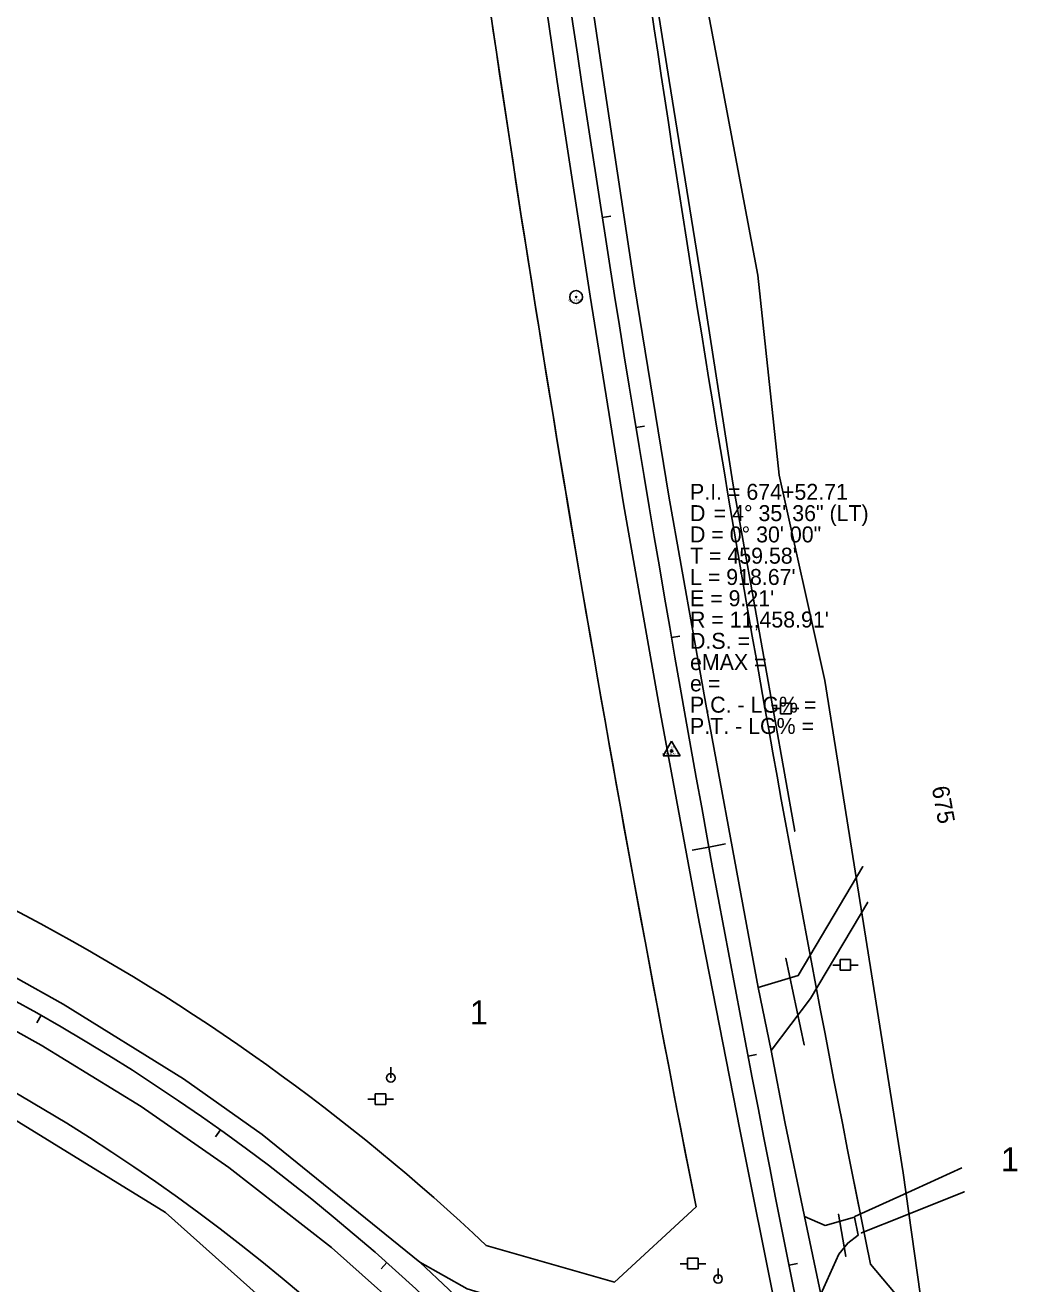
# Model space of a CAD drawing. Extents: x 2519952 to 2531965, y 848341 to 887632.
# Drawn here: x 2523719 to 2524187, y 857916 to 858508 of the extents above; entities that cross this region are included whole.
import ezdxf

# ---------------------------------------------------------------- set-up
doc = ezdxf.new("R2010")
doc.units = 0
for name, color, linetype in [('RD_EX_DR_Pipe', 7, 'Continuous'), ('RD_EX_Driveway', 7, 'Continuous'), ('RD_EX_DV_Prop', 7, 'Continuous'), ('RD_EX_DV_TX_Prop', 7, 'Continuous'), ('RD_EX_Fence_Other', 7, 'Continuous'), ('RD_EX_Road', 7, 'Continuous'), ('RD_EX_RW', 7, 'Continuous'), ('RD_EX_UT', 7, 'Continuous'), ('RD_EX_VEG', 7, 'Continuous'), ('RD_HC_Cl', 7, 'Continuous'), ('RD_HC_Data', 7, 'Continuous'), ('RD_HC_Data_Tic', 7, 'Continuous'), ('RD_HC_Survey_txCode', 7, 'Continuous'), ('RD_HC_TX_Sta50', 7, 'Continuous'), ('RD_HC_txCode', 7, 'Continuous'), ('RD_SMD_Locator', 7, 'Continuous')]:
    doc.layers.add(name, color=color, linetype=linetype)

msp = doc.modelspace()

# ---------------------------------------------------------------- linework, layer by layer
at = {"layer": 'RD_EX_DR_Pipe'}
for p, q in [((2524084.73, 858028.68), (2524076.07, 858069.38)), ((2524104.27, 857929.3), (2524100.83, 857949.12))]:
    msp.add_line(p, q, dxfattribs=at)
at = {"layer": 'RD_EX_Driveway'}
for points in [[(2524063.02, 858055.62), (2524081.9, 858061.29), (2524112.29, 858112.46)], [(2524069.13, 858026.03), (2524087.62, 858050.5), (2524114.54, 858095.72)], [(2524108.43, 857947.98), (2524131.43, 857958.46), (2524158.73, 857970.91)], [(2524111.57, 857940.3), (2524132.07, 857948.51), (2524159.92, 857959.65)], [(2524092.56, 857911.62), (2524100.98, 857930.33), (2524105.25, 857935.59), (2524110.11, 857939.35), (2524108.3, 857947.72), (2524094.5, 857943.84), (2524084.8, 857948.12)]]:
    msp.add_lwpolyline(points, dxfattribs=at)
at = {"layer": 'RD_EX_DV_Prop'}
for p, q in [((2523718.75, 858089.43), (2522948.36, 858496.8)), ((2523995.66, 857917.22), (2524033.94, 857952.52)), ((2523935.39, 857934.44), (2523995.66, 857917.22)), ((2524115.79, 857925.6), (2524172.55, 857858.94))]:
    msp.add_line(p, q, dxfattribs=at)
for centre, radius, start, end in [((2535312.3, 860182.25), 11421.66, 187.82505, 191.395271), ((2535312.3, 860182.25), 11496.66, 187.82505, 191.183137), ((2523254.83, 857212.11), 992.43, 46.70549, 62.13073), ((2523254.83, 857212.11), 917.43, 12.4185, 62.13074)]:
    msp.add_arc(centre, radius, start, end, dxfattribs=at)
at = {"layer": 'RD_EX_Fence_Other'}
msp.add_lwpolyline([(2524080.31, 858129.09), (2524051.13, 858292.53), (2524036.38, 858388.51), (2524021.25, 858481.81), (2524005.1, 858583.36), (2523991.56, 858679.34), (2523981.61, 858745.39), (2523956.83, 858911.5), (2524009.65, 858983.89), (2524009.65, 858983.89), (2524012.84, 858990.17), (2524066.54, 859070.76), (2524113.94, 859137)], dxfattribs=at)
at = {"layer": 'RD_EX_Road'}
for p, q in [((2523990.7, 858479.78), (2523975.78, 858582.23)), ((2523969.29, 858477.11), (2523954.67, 858578.35)), ((2524005.03, 858385.29), (2523990.7, 858479.78)), ((2523984.15, 858380.4), (2523969.29, 858477.11)), ((2524021.05, 858286.44), (2524005.03, 858385.29)), ((2523999.9, 858282.83), (2523984.15, 858380.4)), ((2524038.56, 858188.75), (2524021.05, 858286.44)), ((2524017.21, 858184.41), (2523999.9, 858282.83)), ((2524035.31, 858086.37), (2524017.21, 858184.41)), ((2524056.76, 858089.51), (2524038.56, 858188.75)), ((2524063.02, 858055.62), (2524056.76, 858089.51)), ((2524054.52, 857988.93), (2524035.31, 858086.37)), ((2524069.13, 858026.03), (2524063.02, 858055.62)), ((2524075.65, 857992.49), (2524069.13, 858026.03)), ((2524072.35, 857899.97), (2524054.52, 857988.93)), ((2524084.8, 857948.12), (2524075.65, 857992.49)), ((2524092.56, 857911.62), (2524084.8, 857948.12))]:
    msp.add_line(p, q, dxfattribs=at)
for points in [[(2524083.76, 857706.09), (2524041.21, 857771.75), (2523995.75, 857831.09), (2523964.68, 857866.84), (2523931.43, 857900.94), (2523904.14, 857926.57), (2523830.16, 857986.61), (2523793.14, 858012.75), (2523736.64, 858047.74), (2523691.73, 858072.85), (2523611.63, 858115.77), (2523564.9, 858140.42), (2523547.41, 858149.92), (2523502.6, 858173.74), (2523410.89, 858222.17), (2523313.97, 858273.21), (2523223.1, 858321.44), (2523128.6, 858371), (2523009.6, 858433.8), (2522937.56, 858471.84)], [(2524164.73, 857466.22), (2524145.38, 857525.06), (2524117.67, 857595.18), (2524087.6, 857655.7), (2524082.06, 857665.7), (2524023.34, 857759), (2523979.01, 857816.65), (2523948.37, 857852.22), (2523907.29, 857893.75), (2523862.66, 857933.47), (2523814.36, 857971.03), (2523773.25, 857999.72), (2523726.23, 858028.52), (2523676.55, 858056.09), (2523593.89, 858100.57), (2523579.35, 858108.2), (2523514.46, 858142.71), (2523403, 858201.72), (2523303.54, 858254.06), (2523225.63, 858295.64), (2523117.7, 858352.29), (2523022.81, 858402.31), (2522925.82, 858453.88)], [(2524072.35, 857899.97), (2524073.68, 857887.67), (2524066.59, 857882.36), (2524059.31, 857874.86), (2523976.96, 857898.77), (2523926.46, 857914.07), (2523904.14, 857926.57)]]:
    msp.add_lwpolyline(points, dxfattribs=at)
at = {"layer": 'RD_EX_RW'}
for p, q in [((2523718.75, 858089.43), (2522948.36, 858496.8)), ((2523718.75, 858089.43), (2522948.36, 858496.8)), ((2524172.55, 857858.94), (2524115.79, 857925.6))]:
    msp.add_line(p, q, dxfattribs=at)
msp.add_lwpolyline([(2523935.39, 857934.44), (2523995.66, 857917.22), (2524033.94, 857952.52), (2524030.69, 857969.02)], dxfattribs=at)
for centre, radius, start, end in [((2535312.05, 860182.21), 11421.41, 187.825051, 191.395352), ((2535312.05, 860182.21), 11496.41, 187.825051, 191.099405), ((2523254.83, 857212.11), 992.43, 46.70549, 62.13076), ((2523254.83, 857212.11), 917.43, 12.41849, 62.13076)]:
    msp.add_arc(centre, radius, start, end, dxfattribs=at)
at = {"layer": 'RD_EX_UT'}
for p, q in [((2524078.65, 858189.24), (2524073.65, 858189.24)), ((2524073.65, 858189.24), (2524073.65, 858184.24)), ((2524078.65, 858184.24), (2524078.65, 858189.24)), ((2524070.21, 858186.67), (2524073.68, 858186.67)), ((2524073.65, 858184.24), (2524078.65, 858184.24)), ((2524078.57, 858186.67), (2524082.21, 858186.67)), ((2524098.11, 858066.18), (2524101.58, 858066.18)), ((2524106.54, 858068.74), (2524101.54, 858068.74)), ((2524101.54, 858068.74), (2524101.54, 858063.74)), ((2524106.47, 858066.18), (2524110.11, 858066.18)), ((2524106.54, 858063.74), (2524106.54, 858068.74)), ((2524101.54, 858063.74), (2524106.54, 858063.74)), ((2523890.51, 858013.18), (2523890.51, 858018.18)), ((2523888.23, 858005.74), (2523883.23, 858005.74)), ((2523883.23, 858005.74), (2523883.23, 858000.74)), ((2523888.23, 858000.74), (2523888.23, 858005.74)), ((2523879.8, 858003.18), (2523883.27, 858003.18)), ((2523883.23, 858000.74), (2523888.23, 858000.74)), ((2523888.16, 858003.18), (2523891.8, 858003.18)), ((2524026.46, 857925.89), (2524029.93, 857925.89)), ((2524034.89, 857928.45), (2524029.89, 857928.45)), ((2524029.89, 857928.45), (2524029.89, 857923.45)), ((2524029.89, 857923.45), (2524034.89, 857923.45)), ((2524034.82, 857925.89), (2524038.46, 857925.89)), ((2524034.89, 857923.45), (2524034.89, 857928.45)), ((2524044.24, 857918.69), (2524044.24, 857923.69))]:
    msp.add_line(p, q, dxfattribs=at)
for centre in [(2523890.51, 858013.18), (2524044.24, 857918.69)]:
    msp.add_circle(centre, 2, dxfattribs=at)
at = {"layer": 'RD_EX_VEG'}
for points in [[(2524145.87, 857863.74), (2524131.28, 857968.64), (2524094.37, 858199.86), (2524073.03, 858296.39), (2524062.98, 858390.36), (2524044.77, 858486.65), (2524026.06, 858585.2), (2524012.33, 858681.59), (2523995.08, 858778.35), (2523981.65, 858873.9), (2523966.84, 858971.7), (2523950.88, 859070.39), (2523936.17, 859157.41)], [(2524119.6, 857524.81), (2524064.77, 857652.35), (2523973.59, 857801.07), (2523957.79, 857795.19), (2523784.66, 857949.89), (2523705.5, 857998.68), (2523554.53, 858091.95), (2523523.94, 858046.11)]]:
    msp.add_lwpolyline(points, dxfattribs=at)
at = {"layer": 'RD_HC_Cl'}
for centre, radius, start, end in [((2535312.05, 860182.21), 11458.91, 187.825051, 192.418483), ((2523254.83, 857212.11), 954.93, 12.41849, 62.13076)]:
    msp.add_arc(centre, radius, start, end, dxfattribs=at)
at = {"layer": 'RD_HC_Data'}
for p, q in [((2524018.44, 858164.51), (2524022.42, 858171.39)), ((2524022.42, 858171.39), (2524026.39, 858164.51)), ((2524018.44, 858164.51), (2524026.39, 858164.51))]:
    msp.add_line(p, q, dxfattribs=at)
for centre, radius in [((2523977.58, 858380.04), 3), ((2523977.58, 858380.04), 0.282), ((2524022.42, 858166.8), 0.529)]:
    msp.add_circle(centre, radius, dxfattribs=at)
at = {"layer": 'RD_HC_Data_Tic'}
for p, q in [((2523989.86, 858417.42), (2523993.81, 858418.04)), ((2524005.69, 858318.68), (2524009.64, 858319.33)), ((2524022.38, 858220.08), (2524026.32, 858220.77)), ((2524039.94, 858121.64), (2524032.07, 858120.2)), ((2524039.94, 858121.64), (2524047.81, 858123.08)), ((2523726.24, 858042.57), (2523724.27, 858039.09)), ((2524058.35, 858023.35), (2524062.28, 858024.1)), ((2523810.47, 857988.74), (2523808.14, 857985.49)), ((2523888.61, 857926.41), (2523885.95, 857923.42)), ((2524077.62, 857925.22), (2524081.54, 857926.01))]:
    msp.add_line(p, q, dxfattribs=at)
at = {"layer": 'RD_SMD_Locator'}
for centre in [(2524044.77, 858486.65), (2523990.7, 858479.78), (2524021.25, 858481.81), (2523969.29, 858477.11), (2524062.98, 858390.36), (2524005.03, 858385.29), (2524036.38, 858388.51), (2523977.58, 858380.04), (2523984.15, 858380.4), (2524073.03, 858296.39), (2524051.13, 858292.53), (2524021.05, 858286.44), (2523999.9, 858282.83), (2524094.37, 858199.86), (2524017.21, 858184.41), (2524038.56, 858188.75), (2524022.42, 858166.8), (2524080.31, 858129.09), (2524112.29, 858112.46), (2524114.54, 858095.72), (2524056.76, 858089.51), (2524035.31, 858086.37), (2524076.07, 858069.38), (2524081.9, 858061.29), (2524063.02, 858055.62), (2524063.02, 858055.62), (2523736.64, 858047.74), (2524087.62, 858050.5), (2523726.23, 858028.52), (2524069.13, 858026.03), (2524069.13, 858026.03), (2524084.73, 858028.68), (2523793.14, 858012.75), (2523773.25, 857999.72), (2524054.52, 857988.93), (2524075.65, 857992.49), (2523830.16, 857986.61), (2523814.36, 857971.03), (2524158.73, 857970.91), (2524131.28, 857968.64), (2524131.43, 857958.46), (2524159.92, 857959.65), (2523784.66, 857949.89), (2524084.8, 857948.12), (2524084.8, 857948.12), (2524100.83, 857949.12), (2524108.3, 857947.72), (2524108.43, 857947.98), (2524132.07, 857948.51), (2524094.5, 857943.84), (2524105.25, 857935.59), (2524110.11, 857939.35), (2524111.57, 857940.3), (2523862.66, 857933.47), (2524100.98, 857930.33), (2524104.27, 857929.3), (2523904.14, 857926.57), (2523904.14, 857926.57)]:
    msp.add_circle(centre, 0.001, dxfattribs=at)

# ---------------------------------------------------------------- texts
at = {"layer": 'RD_EX_DV_TX_Prop'}
for p in [(2523927.66, 858038.27), (2524177.18, 857969.22)]:
    msp.add_text('1', height=11.32, dxfattribs=at).set_placement(p)
at = {"layer": 'RD_HC_Survey_txCode'}
for s, p in [('P.I. = 674+52.71', (2524031.08, 858284.77)), ('D', (2524031.08, 858274.77)), ('    = 4%%d 35\' 36" (LT)', (2524031.08, 858274.77)), ('D = 0%%d 30\' 00"', (2524031.08, 858264.77)), ("T = 459.58'", (2524031.08, 858254.77)), ("L = 918.67'", (2524031.08, 858244.77)), ("E = 9.21'", (2524031.08, 858234.77)), ("R = 11,458.91'", (2524031.08, 858224.77)), ('D.S. = ', (2524031.08, 858214.77)), ('eMAX = ', (2524031.08, 858204.77)), ('e = ', (2524031.08, 858194.77)), ('P.C. - LG% = ', (2524031.08, 858184.77)), ('P.T. - LG% = ', (2524031.08, 858174.77))]:
    msp.add_text(s, height=7.5, dxfattribs=at).set_placement(p)
at = {"layer": 'RD_HC_TX_Sta50'}
msp.add_text('675', height=8, rotation=280.35946, dxfattribs=at).set_placement((2524144.61, 858149.62))
at = {"layer": 'RD_HC_txCode'}
for s, p in [('CP 4 PSC', (2523974.01, 858378.04)), ('4', (2523977.29, 858381.04)), ('PI 674+52.71', (2524018.16, 858164.8)), ('12', (2524021.97, 858167.8))]:
    msp.add_text(s, height=1, dxfattribs=at).set_placement(p)

doc.saveas('drawing.dxf')
